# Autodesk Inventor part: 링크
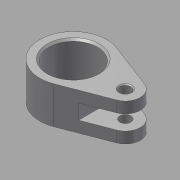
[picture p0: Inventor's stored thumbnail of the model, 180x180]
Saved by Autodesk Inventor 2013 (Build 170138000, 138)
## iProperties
Created: 2015-12
Part Number: 링크
Material: 강철, 연강
Document SubType Name: Modeling
Designer: mduedu
Density: 7.86 g/cm^3
Author: mduedu
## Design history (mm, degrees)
sketch "스케치1"
  geometry: L1 (6.429, -16.813)-(30.857, -7.472); L2 (6.429, 16.813)-(30.857, 7.472); A1 r 18 centre (0, 0) between (6.429, 16.813) and (6.429, -16.813); A2 r 8 centre (28, 0) between (30.857, -7.472) and (30.857, 7.472); 1 further point
  constraints: 4 end point, 4 point on circle, 4 tangent, 2 centre point, 1 coincident, 1 horizontal alignment
  dimensions: "d0" = 18 radius of A1; "d1" = 8 radius of A2; "d2" = 28 distance of A2.centre point (0, 0)
extrude "돌출1" new body sketch "스케치1" stored distance "d3" = 20; taper "d4" = 0 deg
sketch "스케치2"
  geometry: L1 (6.429, 16.813)-(30.857, 7.472) reference; L2 (30.857, -7.472)-(6.429, -16.813) reference; L3 (16, 13.153)-(16, -13.153); A1 r 8 centre (28, 0) between (30.857, -7.472) and (30.857, 7.472) reference; 1 further point
  constraints: 2 end point, 2 point on line, 1 vertical
  dimensions: "d5" = 20 dimension on A1 L3
extrude "돌출2" cut sketch "스케치2" stored distance "d6" = 8; taper "d7" = 0 deg
hole "구멍1" diameter "d10" = 26; stored, may be unused: countersink angle "d14" = 90 deg, drill point angle "d16" = 118 deg; dims "d8" = 10, "d9" = 10, "d11" = 6, "d12" = 4, "d13" = 2, "d15" = 8
hole "구멍2" diameter "d19" = 6; stored, may be unused: countersink angle "d23" = 90 deg, drill point angle "d25" = 118 deg; dims "d20" = 6, "d21" = 4, "d22" = 2, "d24" = 8, "d32" = 10, "d33" = 10
chamfer "모따기1" distance "d26" = 1; stored, may be unused: second distance "d27" = 2, angle "d28" = 45 deg
chamfer "모따기2" distance "d29" = 0.5; stored, may be unused: second distance "d30" = 2, angle "d31" = 45 deg
node "솔리드1"
